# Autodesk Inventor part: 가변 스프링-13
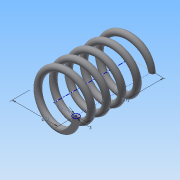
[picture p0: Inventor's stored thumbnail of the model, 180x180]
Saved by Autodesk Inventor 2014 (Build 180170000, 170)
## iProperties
Created: 2015-09
Part Number: 가변 스프링-13
Material: 강철, 탄소
Document SubType Name: Modeling
Designer: study
Density: 7.87 g/cm^3
Appearance: 반연마
Mass: 18.6318 g
Surface Area: 32.4192 cm^2
Volume: 2.36745 cm^3
Author: study
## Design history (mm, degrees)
sketch "스케치1"
  geometry: L1 (0, 0)-(11, 0); L2 (11, 0)-(11, 25.358); L3 (11, 25.358)-(0, 25.358); L4 (0, 25.358)-(0, 0); C1 r 1.5 at (11, 0)
  constraints: 8 end point, 2 parallel, 1 centre point, 1 coincident, 1 horizontal, 1 perpendicular
  dimensions: "d0" = 25.35829 distance of L1.end L2.end (derived); "d1" = 22 diameter of L1.end L4; "d2" = 3 diameter of C1
feature "코일1" sketch "스케치1" pitch "d3" = 10; turns "d5" = 5; dims "d4" = 25.35829 (= d0), "d6" = 0, angle "d7" = 90 deg, angle "d8" = 90 deg, "d9" = 0, "d10" = 0
node "작업 평면1"
sketch "스케치2"
  geometry: L1 (-12.5, 0)-(-9.5, 0) reference; 1 further point
  constraints: 1 horizontal alignment
extrude "돌출1" cut sketch "스케치2" stored distance "d12" = 10; taper "d13" = 0 deg
node "작업 평면2"
sketch "스케치3"
  geometry: L1 (-9.5, 0)-(-12.5, 0) reference; 1 further point
  constraints: 1 horizontal alignment
extrude "돌출2" cut sketch "스케치3" stored distance "d15" = 10; taper "d16" = 0 deg
node "솔리드1"
node "절단 모서리 투영1"
node "절단 모서리 투영2"
other parameters: "d11" = 0, "d14" = 25.35829 (= d0)
